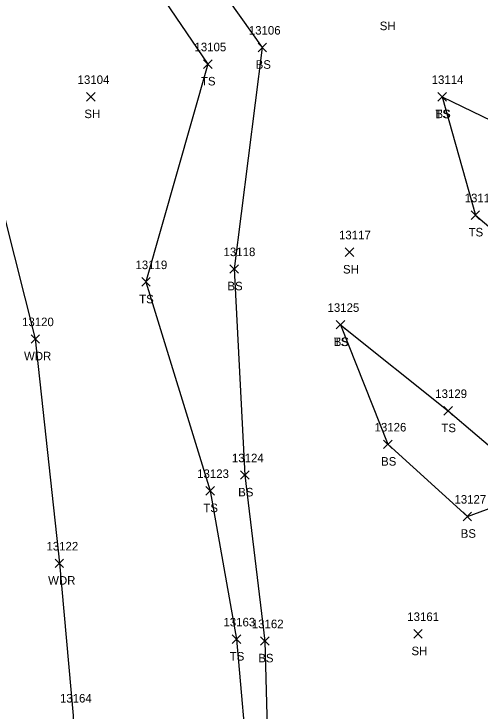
# Model space of a CAD drawing. Extents: x 1482574 to 1485769, y 580696 to 595649.
# Drawn here: x 1483889.9 to 1483999, y 583429.1 to 583592.2 of the extents above; entities that cross this region are included whole.
import ezdxf

# ---------------------------------------------------------------- set-up
doc = ezdxf.new("R2010")
doc.units = 0
for name, color, linetype in [('L_A', 7, 'Continuous'), ('L_I', 7, 'Continuous'), ('L_TIC', 7, 'Continuous'), ('LAWA', 7, 'Continuous'), ('LELB', 7, 'Continuous')]:
    doc.layers.add(name, color=color, linetype=linetype)

msp = doc.modelspace()

# ---------------------------------------------------------------- linework, layer by layer
at = {"layer": 'L_TIC'}
for points in [[(1483947.02, 583583.38), (1483949.02, 583585.38)], [(1483949.02, 583583.38), (1483947.02, 583585.38)], [(1483934.25, 583579.48), (1483936.25, 583581.48)], [(1483936.25, 583579.48), (1483934.25, 583581.48)], [(1483906.89, 583571.83), (1483908.89, 583573.83)], [(1483908.89, 583571.83), (1483906.89, 583573.83)], [(1483989.1, 583571.82), (1483991.1, 583573.82)], [(1483991.1, 583571.82), (1483989.1, 583573.82)], [(1483989.1, 583571.82), (1483991.1, 583573.82)], [(1483991.1, 583571.82), (1483989.1, 583573.82)], [(1483996.88, 583544.14), (1483998.88, 583546.14)], [(1483998.88, 583544.14), (1483996.88, 583546.14)], [(1483967.41, 583535.46), (1483969.41, 583537.46)], [(1483969.41, 583535.46), (1483967.41, 583537.46)], [(1483940.41, 583531.53), (1483942.41, 583533.53)], [(1483942.41, 583531.53), (1483940.41, 583533.53)], [(1483919.79, 583528.49), (1483921.79, 583530.49)], [(1483921.79, 583528.49), (1483919.79, 583530.49)], [(1483965.3, 583518.48), (1483967.3, 583520.48)], [(1483967.3, 583518.48), (1483965.3, 583520.48)], [(1483965.3, 583518.48), (1483967.3, 583520.48)], [(1483967.3, 583518.48), (1483965.3, 583520.48)], [(1483893.89, 583515.14), (1483895.89, 583517.14)], [(1483895.89, 583515.14), (1483893.89, 583517.14)], [(1483990.52, 583498.33), (1483992.52, 583500.33)], [(1483992.52, 583498.33), (1483990.52, 583500.33)], [(1483976.37, 583490.49), (1483978.37, 583492.49)], [(1483978.37, 583490.49), (1483976.37, 583492.49)], [(1483942.93, 583483.29), (1483944.93, 583485.29)], [(1483944.93, 583483.29), (1483942.93, 583485.29)], [(1483934.8, 583479.6), (1483936.8, 583481.6)], [(1483936.8, 583479.6), (1483934.8, 583481.6)], [(1483995.01, 583473.61), (1483997.01, 583475.61)], [(1483997.01, 583473.61), (1483995.01, 583475.61)], [(1483899.52, 583462.64), (1483901.52, 583464.64)], [(1483901.52, 583462.64), (1483899.52, 583464.64)], [(1483983.44, 583446.13), (1483985.44, 583448.13)], [(1483985.44, 583446.13), (1483983.44, 583448.13)], [(1483940.99, 583444.87), (1483942.99, 583446.87)], [(1483942.99, 583444.87), (1483940.99, 583446.87)], [(1483947.63, 583444.45), (1483949.63, 583446.45)], [(1483949.63, 583444.45), (1483947.63, 583446.45)]]:
    msp.add_lwpolyline(points, dxfattribs=at)
at = {"layer": 'LAWA'}
msp.add_lwpolyline([(1483803.2, 583735.12), (1483825.14, 583713.33), (1483843.38, 583669.74), (1483862.33, 583628.74), (1483871.69, 583603.07), (1483882.64, 583564.44), (1483894.89, 583516.14), (1483900.52, 583463.64), (1483903.73, 583428.05), (1483902.34, 583384.57), (1483914.38, 583350.08), (1483921.77, 583324.12), (1483930.55, 583295.67), (1483924.87, 583287.8)], dxfattribs=at)
at = {"layer": 'LELB'}
for points in [[(1483764.89, 583869.31), (1483766.47, 583848.33), (1483773.02, 583835.43), (1483788.15, 583817.33), (1483797.07, 583803.46), (1483802.69, 583789.66), (1483809.82, 583753.25), (1483830.69, 583716.93), (1483860.8, 583678.02), (1483884.63, 583637.37), (1483911.6, 583615.28), (1483935.25, 583580.48), (1483920.79, 583529.49), (1483935.8, 583480.6), (1483941.99, 583445.87), (1483944.83, 583413.13), (1483940.65, 583358.64), (1483945.14, 583321.38), (1483963.19, 583281.99)], [(1483806.98, 583791.11), (1483811.44, 583753.6), (1483836.28, 583720.23), (1483869.17, 583683.74), (1483895.56, 583644.56), (1483921.85, 583621.21), (1483948.02, 583584.38), (1483941.41, 583532.53), (1483943.93, 583484.29), (1483948.63, 583445.45), (1483949.51, 583410.64), (1483944.14, 583359.56), (1483947.93, 583324.11), (1483965.59, 583284.09)], [(1483990.1, 583572.82), (1484022.72, 583557.08), (1484046.98, 583528.45), (1484042.02, 583516.42), (1484043.08, 583507.53), (1484067.2, 583468.65), (1484079.55, 583425.02), (1484086.3, 583397.24)], [(1483990.1, 583572.82), (1483997.88, 583545.14), (1484027.51, 583519.95), (1484046.98, 583528.45), (1484047.92, 583518.29), (1484045.68, 583508.91), (1484070.79, 583469.65), (1484085.92, 583425.09), (1484092.97, 583397.84)], [(1483966.3, 583519.48), (1483991.52, 583499.33), (1484005.08, 583487.81), (1484017.32, 583510.31), (1484027.51, 583519.95)], [(1483966.3, 583519.48), (1483977.37, 583491.49), (1483996.01, 583474.61), (1484010.82, 583480.08), (1484020.74, 583508.37), (1484027.32, 583512.52), (1484032.85, 583511.76), (1484040.2, 583505.31), (1484064.43, 583466.89), (1484075.06, 583424.42), (1484074.61, 583392.28)]]:
    msp.add_lwpolyline(points, dxfattribs=at)

# ---------------------------------------------------------------- texts
at = {"layer": 'L_A'}
for s, p in [('SH', (1483975.5, 583588.42)), ('BS', (1483946.46, 583579.38)), ('TS', (1483933.65, 583575.48)), ('SH', (1483906.38, 583567.83)), ('TS', (1483988.51, 583567.82)), ('BS', (1483988.55, 583567.82)), ('TS', (1483996.29, 583540.14)), ('SH', (1483966.9, 583531.46)), ('BS', (1483939.85, 583527.53)), ('TS', (1483919.2, 583524.49)), ('TS', (1483964.71, 583514.48)), ('BS', (1483964.74, 583514.48)), ('WDR', (1483892.25, 583511.14)), ('TS', (1483989.93, 583494.33)), ('BS', (1483975.81, 583486.49)), ('BS', (1483942.37, 583479.29)), ('TS', (1483934.21, 583475.6)), ('BS', (1483994.45, 583469.61)), ('WDR', (1483897.89, 583458.64)), ('TS', (1483940.4, 583440.87)), ('SH', (1483982.93, 583442.13)), ('BS', (1483947.07, 583440.45))]:
    msp.add_text(s, height=2, dxfattribs=at).set_placement(p)
at = {"layer": 'L_I'}
for s, p in [('13106', (1483944.86, 583587.38)), ('13105', (1483932.14, 583583.48)), ('13104', (1483904.79, 583575.83)), ('13114', (1483987.65, 583575.82)), ('13114', (1483987.65, 583575.82)), ('13116', (1483995.37, 583548.14)), ('13117', (1483965.96, 583539.46)), ('13118', (1483938.95, 583535.53)), ('13119', (1483918.33, 583532.49)), ('13125', (1483963.28, 583522.48)), ('13125', (1483963.28, 583522.48)), ('13120', (1483891.78, 583519.14)), ('13129', (1483988.49, 583502.33)), ('13126', (1483974.29, 583494.49)), ('13124', (1483940.91, 583487.29)), ('13123', (1483932.77, 583483.6)), ('13127', (1483992.98, 583477.61)), ('13122', (1483897.5, 583466.64)), ('13161', (1483981.94, 583450.13)), ('13163', (1483938.92, 583448.87)), ('13162', (1483945.56, 583448.45)), ('13164', (1483900.66, 583431.05))]:
    msp.add_text(s, height=2, dxfattribs=at).set_placement(p)

doc.saveas('drawing.dxf')
